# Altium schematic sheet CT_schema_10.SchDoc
size 382 x 278 mm
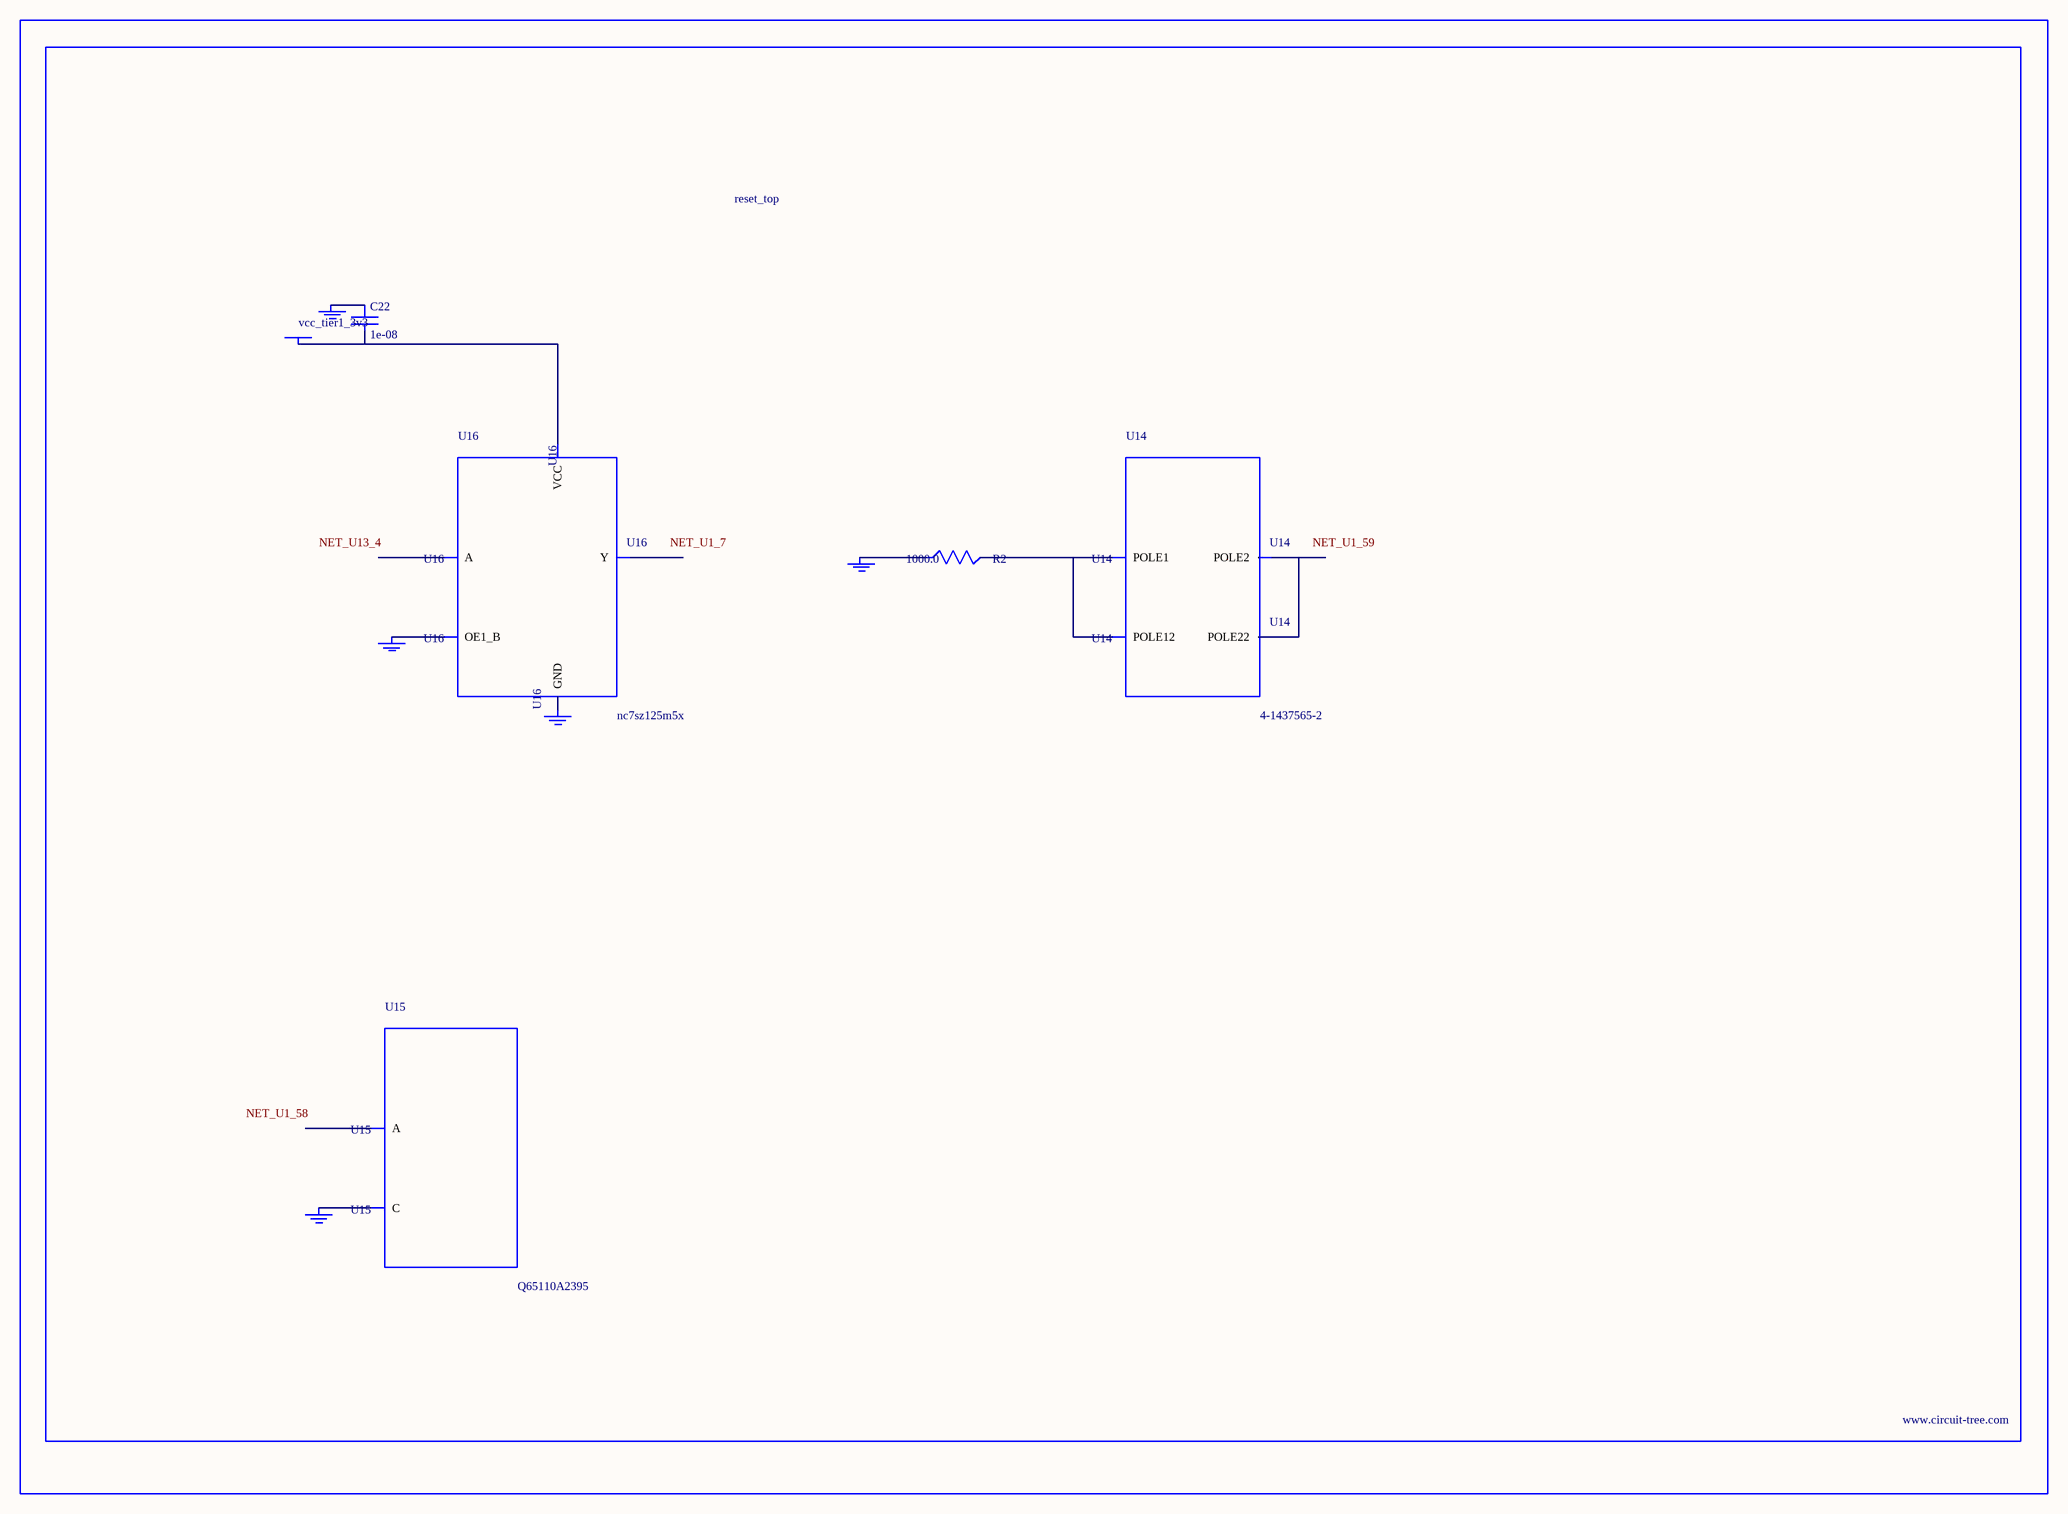
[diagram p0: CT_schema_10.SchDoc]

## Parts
BORDER9  (no value)
C22  1e-08  [C0402]
GND_INSTANCE_9_0  (no value)
GND_INSTANCE_9_1  (no value)
GND_INSTANCE_9_2  (no value)
GND_INSTANCE_9_3  (no value)
GND_INSTANCE_9_4  (no value)
POWER_INSTANCE_9_0  vcc_tier1_3v3
R2  1000.0  [R0603]
U14  4-1437565-2  [SW_4-1437565-2]
U15  Q65110A2395  [LGM67K-G1J2-24-Z]
U16  nc7sz125m5x  [NC7SZ125M5X]

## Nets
NetC22_1: C22.1 GND_INSTANCE_9_2.0(GND)
NetC22_2: C22.2 POWER_INSTANCE_9_0.0(PWR) U16.5(VCC)
NetGND_INSTANCE_9_0_0: GND_INSTANCE_9_0.0(GND) R2.1
NetGND_INSTANCE_9_1_0: GND_INSTANCE_9_1.0(GND) U15.C
NetGND_INSTANCE_9_3_0: GND_INSTANCE_9_3.0(GND) U16.1(OE1_B)
NetGND_INSTANCE_9_4_0: GND_INSTANCE_9_4.0(GND) U16.3(GND)
NetR2_2: R2.2 U14.1(POLE1) U14.2(POLE12)
NetU14_3: U14.3(POLE2) U14.4(POLE22)

Not connected (* = marked no-connect by the designer): U15 A; U16 2(A) 4(Y)

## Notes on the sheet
- Labels drawn without touching a wire or pin: NET_U1_7, NET_U1_58, NET_U1_59, NET_U13_4

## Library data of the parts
BORDER9 = BORDER_PAGE9
C22 = C0402C103K3RAC
GND_INSTANCE_9_0-GND_INSTANCE_9_4 = GND
POWER_INSTANCE_9_0 = PWR
R2 = RC0603JR-071KL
